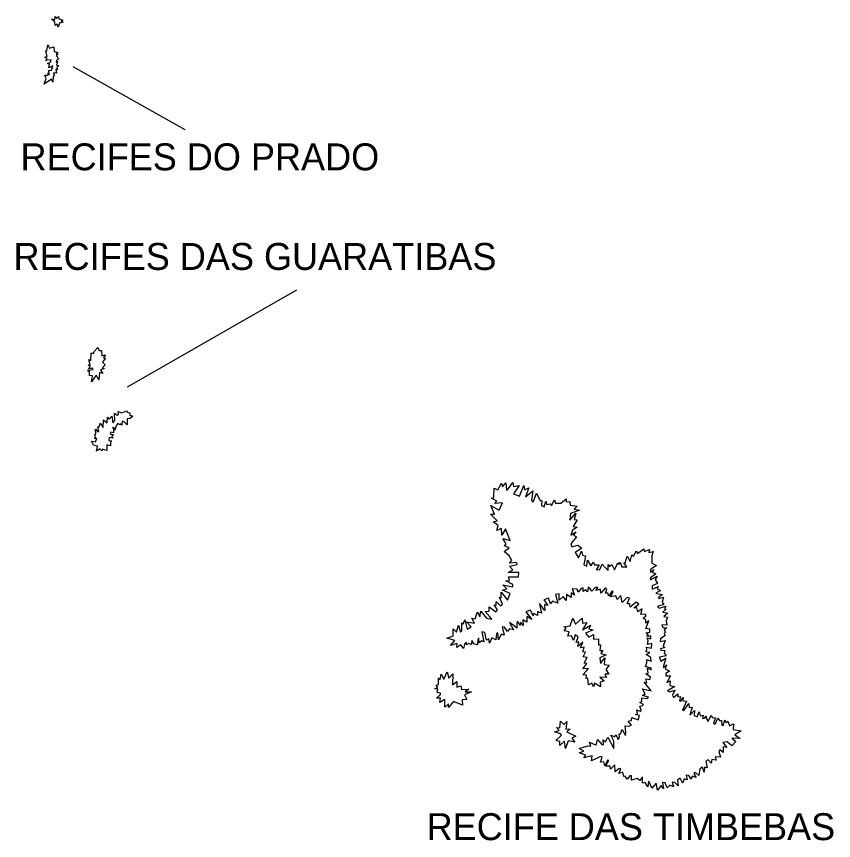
# Model space of a CAD drawing. Extents: x 662444 to 1640468, y 7452018 to 9606170.
# Drawn here: x 1121412 to 1141261, y 8052663 to 8072685 of the extents above; entities that cross this region are included whole.
import ezdxf

# ---------------------------------------------------------------- set-up
doc = ezdxf.new("R2010")
doc.units = 0
doc.layers.add('Level 1', color=7, linetype='Continuous')
doc.layers.add('Level 3', color=7, linetype='Continuous')

msp = doc.modelspace()

# ---------------------------------------------------------------- linework, layer by layer
at = {"layer": 'Level 1'}
for p, q in [((1125507, 8069931), (1122785, 8071458)), ((1128214, 8066038), (1124104, 8063682))]:
    msp.add_line(p, q, dxfattribs=at)
for points in [[(1122260, 8072631), (1122347, 8072603), (1122350, 8072685), (1122387, 8072635), (1122432, 8072685), (1122440, 8072626), (1122537, 8072593), (1122500, 8072576), (1122543, 8072544), (1122458, 8072523), (1122427, 8072429), (1122400, 8072497), (1122351, 8072467), (1122345, 8072550), (1122260, 8072631)], [(1122137, 8071178), (1122101, 8071261), (1122167, 8071259), (1122214, 8071294), (1122169, 8071303), (1122208, 8071325), (1122191, 8071374), (1122263, 8071382), (1122294, 8071487), (1122200, 8071440), (1122213, 8071529), (1122167, 8071546), (1122240, 8071575), (1122257, 8071634), (1122120, 8071613), (1122160, 8071649), (1122102, 8071694), (1122160, 8071716), (1122126, 8071847), (1122152, 8071848), (1122177, 8071996), (1122216, 8071913), (1122320, 8071947), (1122324, 8071834), (1122416, 8071813), (1122378, 8071776), (1122422, 8071772), (1122375, 8071732), (1122440, 8071659), (1122382, 8071620), (1122379, 8071579), (1122410, 8071596), (1122384, 8071504), (1122438, 8071498), (1122393, 8071443), (1122412, 8071393), (1122364, 8071395), (1122384, 8071307), (1122315, 8071317), (1122329, 8071256), (1122307, 8071227), (1122296, 8071088), (1122259, 8071160), (1122085, 8071044), (1122137, 8071178)], [(1123412, 8063854), (1123348, 8063969), (1123238, 8063811), (1123255, 8063956), (1123186, 8063960), (1123184, 8064041), (1123138, 8064082), (1123272, 8064107), (1123260, 8064138), (1123162, 8064118), (1123210, 8064183), (1123155, 8064213), (1123201, 8064214), (1123169, 8064352), (1123221, 8064325), (1123227, 8064515), (1123287, 8064493), (1123302, 8064544), (1123387, 8064642), (1123423, 8064568), (1123480, 8064572), (1123483, 8064436), (1123571, 8064462), (1123529, 8064391), (1123576, 8064383), (1123505, 8064288), (1123567, 8064222), (1123499, 8064154), (1123539, 8064131), (1123457, 8064099), (1123511, 8064014), (1123427, 8064034), (1123412, 8063854)], [(1123282, 8062267), (1123238, 8062365), (1123334, 8062350), (1123363, 8062434), (1123304, 8062435), (1123335, 8062462), (1123319, 8062527), (1123337, 8062537), (1123333, 8062660), (1123378, 8062604), (1123414, 8062599), (1123390, 8062714), (1123424, 8062716), (1123441, 8062805), (1123516, 8062696), (1123528, 8062884), (1123613, 8062808), (1123620, 8062948), (1123660, 8062901), (1123731, 8062976), (1123754, 8062814), (1123802, 8062869), (1123797, 8063049), (1123854, 8062999), (1123889, 8063026), (1123886, 8063090), (1123974, 8063052), (1124093, 8063102), (1124100, 8063069), (1124169, 8063057), (1124167, 8063000), (1124235, 8062973), (1124173, 8062914), (1124101, 8062908), (1124097, 8062762), (1124024, 8062832), (1123981, 8062855), (1123968, 8062755), (1123929, 8062786), (1123928, 8062761), (1123878, 8062794), (1123840, 8062754), (1123802, 8062652), (1123772, 8062707), (1123741, 8062680), (1123814, 8062644), (1123765, 8062640), (1123766, 8062569), (1123703, 8062585), (1123688, 8062545), (1123765, 8062518), (1123731, 8062496), (1123749, 8062438), (1123665, 8062453), (1123659, 8062380), (1123732, 8062372), (1123696, 8062340), (1123693, 8062255), (1123610, 8062279), (1123605, 8062138), (1123491, 8062172), (1123488, 8062130), (1123433, 8062183), (1123354, 8062121), (1123380, 8062246), (1123282, 8062267)], [(1132204, 8057419), (1132108, 8057352), (1132116, 8057454), (1131953, 8057404), (1132061, 8057522), (1131868, 8057578), (1132018, 8057636), (1132018, 8057807), (1132105, 8057726), (1132151, 8057899), (1132198, 8057726), (1132229, 8057761), (1132229, 8057950), (1132262, 8057919), (1132301, 8058022), (1132361, 8057798), (1132460, 8057857), (1132343, 8057980), (1132542, 8057943), (1132473, 8058069), (1132555, 8058046), (1132614, 8058218), (1132666, 8058096), (1132693, 8058234), (1132830, 8058064), (1132959, 8058045), (1132917, 8058087), (1132795, 8058226), (1132893, 8058236), (1132896, 8058338), (1133060, 8058222), (1133095, 8058269), (1133020, 8058389), (1133064, 8058385), (1133069, 8058474), (1133173, 8058366), (1133219, 8058409), (1133144, 8058572), (1133187, 8058558), (1133183, 8058696), (1133337, 8058506), (1133403, 8058667), (1133223, 8058742), (1133323, 8058780), (1133226, 8058877), (1133473, 8058824), (1133469, 8058885), (1133300, 8058970), (1133388, 8058982), (1133362, 8059073), (1133611, 8059071), (1133618, 8059179), (1133358, 8059176), (1133470, 8059239), (1133387, 8059331), (1133573, 8059369), (1133566, 8059415), (1133392, 8059402), (1133445, 8059464), (1133379, 8059584), (1133262, 8059685), (1133384, 8059773), (1133268, 8059823), (1133310, 8059870), (1133224, 8060005), (1133407, 8059952), (1133290, 8060239), (1133206, 8060083), (1133192, 8060242), (1133080, 8060197), (1133115, 8060318), (1132989, 8060409), (1133090, 8060429), (1132927, 8060592), (1133027, 8060592), (1132938, 8060802), (1133142, 8060686), (1133220, 8060865), (1133034, 8060852), (1133082, 8060910), (1132949, 8060983), (1133008, 8060994), (1133014, 8061224), (1133019, 8061224), (1133110, 8061184), (1133194, 8061342), (1133222, 8061255), (1133302, 8061350), (1133320, 8061177), (1133344, 8061187), (1133467, 8061358), (1133487, 8061267), (1133621, 8061292), (1133487, 8061086), (1133629, 8061026), (1133736, 8061289), (1133751, 8061184), (1133858, 8061229), (1133779, 8061011), (1133953, 8061157), (1133921, 8060928)], [(1133921, 8060928), (1133966, 8060885), (1134044, 8061099), (1134131, 8060917), (1134172, 8060921), (1134164, 8060801), (1134229, 8060768), (1134272, 8060910), (1134300, 8060830), (1134378, 8060847), (1134412, 8060802), (1134485, 8060938), (1134508, 8060863), (1134639, 8060858), (1134766, 8060966), (1134763, 8060895), (1134859, 8060902), (1134861, 8060811), (1135037, 8060790), (1134963, 8060717), (1135091, 8060689), (1134873, 8060612), (1134856, 8060449), (1134999, 8060617), (1134961, 8060459), (1135030, 8060453), (1134939, 8060289), (1135033, 8060273), (1134923, 8060205), (1134877, 8060080), (1135004, 8060164), (1134946, 8060084), (1135018, 8060040), (1134879, 8059868), (1134900, 8059798), (1135046, 8059840), (1135144, 8059766), (1134985, 8059658), (1135063, 8059531), (1135135, 8059694), (1135160, 8059594), (1135239, 8059584), (1135195, 8059363), (1135266, 8059333), (1135288, 8059478), (1135364, 8059338), (1135427, 8059428), (1135456, 8059358), (1135569, 8059360), (1135499, 8059242), (1135586, 8059247), (1135638, 8059379), (1135716, 8059298), (1135790, 8059226), (1135790, 8059366), (1135817, 8059322), (1135872, 8059367), (1135937, 8059243), (1136022, 8059414), (1136044, 8059367), (1136075, 8059425), (1136116, 8059309), (1136236, 8059311), (1136168, 8059410), (1136203, 8059409), (1136249, 8059575), (1136325, 8059446), (1136365, 8059604), (1136406, 8059575), (1136471, 8059701), (1136496, 8059639), (1136654, 8059752), (1136659, 8059688), (1136789, 8059738), (1136771, 8059659), (1136882, 8059687), (1136849, 8059586), (1136849, 8059401), (1136960, 8059342), (1136820, 8059254), (1136819, 8059231), (1136815, 8059177), (1136898, 8059246), (1136858, 8059186), (1136942, 8059143), (1136818, 8059049), (1136812, 8058995), (1136973, 8059086), (1136928, 8059002), (1136982, 8058906), (1136857, 8058851), (1136854, 8058767), (1137000, 8058839), (1136975, 8058776), (1137056, 8058740), (1136941, 8058677), (1136964, 8058666), (1137104, 8058637), (1137010, 8058570), (1137017, 8058545), (1137128, 8058572)], [(1136248, 8058414), (1136305, 8058554), (1136252, 8058569), (1136126, 8058449), (1136095, 8058618), (1136009, 8058516), (1135976, 8058612), (1135842, 8058587), (1135904, 8058709), (1135885, 8058727), (1135800, 8058601), (1135778, 8058670), (1135719, 8058670), (1135752, 8058761), (1135723, 8058800), (1135609, 8058676), (1135597, 8058768), (1135483, 8058738), (1135536, 8058814), (1135474, 8058807), (1135392, 8058723), (1135352, 8058775), (1135300, 8058817), (1135287, 8058707), (1135247, 8058757), (1135182, 8058710), (1135179, 8058801), (1135128, 8058789), (1135059, 8058701), (1135032, 8058771), (1134915, 8058777), (1134972, 8058621), (1134886, 8058685), (1134884, 8058565), (1134773, 8058638), (1134766, 8058492), (1134692, 8058591), (1134600, 8058504), (1134599, 8058660), (1134506, 8058639), (1134562, 8058433), (1134435, 8058478), (1134382, 8058410), (1134334, 8058552), (1134223, 8058507), (1134322, 8058374), (1134243, 8058394), (1134244, 8058253), (1134118, 8058424), (1134136, 8058333), (1134168, 8058188), (1134069, 8058229), (1134067, 8058132), (1133976, 8058175), (1133964, 8058120), (1133901, 8058257), (1133790, 8058217), (1133931, 8058031), (1133810, 8058104), (1133813, 8057968), (1133713, 8058024), (1133719, 8057889), (1133654, 8057972), (1133650, 8057893), (1133587, 8057990), (1133569, 8057933), (1133566, 8057823), (1133504, 8057882), (1133388, 8057959), (1133486, 8057785), (1133392, 8057803), (1133344, 8057742), (1133269, 8057847), (1133213, 8057853), (1133262, 8057655), (1133188, 8057675), (1133120, 8057536), (1133109, 8057709), (1133073, 8057686), (1133054, 8057541), (1132960, 8057584), (1132905, 8057462), (1132888, 8057565), (1132828, 8057532), (1132792, 8057714), (1132716, 8057736), (1132763, 8057493), (1132720, 8057517), (1132652, 8057465), (1132645, 8057580), (1132621, 8057550), (1132609, 8057415), (1132523, 8057438), (1132474, 8057526), (1132459, 8057422), (1132403, 8057454), (1132345, 8057420), (1132342, 8057471), (1132308, 8057457), (1132271, 8057330), (1132204, 8057419)], [(1137128, 8058572), (1137102, 8058457), (1137139, 8058401), (1136986, 8058349), (1137024, 8058309), (1137184, 8058360), (1137154, 8058290), (1137195, 8058287), (1137113, 8058215), (1137239, 8058185), (1137139, 8058104), (1137228, 8058093), (1137194, 8058000), (1137209, 8057899), (1137094, 8057903), (1137113, 8057841), (1137212, 8057828), (1137150, 8057781), (1137177, 8057729), (1137145, 8057689), (1137174, 8057644), (1137055, 8057566), (1137050, 8057502), (1137174, 8057524), (1137121, 8057384), (1137166, 8057351), (1137058, 8057323), (1137065, 8057284), (1137164, 8057281), (1137145, 8057222), (1137194, 8057150), (1137036, 8057116), (1137065, 8057022), (1137187, 8057091), (1137133, 8056911), (1137132, 8056857), (1137201, 8056929), (1137172, 8056833), (1137273, 8056775), (1137185, 8056721), (1137190, 8056661), (1137300, 8056661), (1137212, 8056502), (1137294, 8056540), (1137284, 8056426), (1137403, 8056402), (1137231, 8056302), (1137278, 8056273), (1137409, 8056315), (1137352, 8056194), (1137376, 8056139), (1137478, 8056226), (1137479, 8056157), (1137541, 8056160), (1137518, 8056064), (1137542, 8056040), (1137606, 8056140), (1137604, 8056061), (1137686, 8056051), (1137590, 8055829), (1137621, 8055822), (1137746, 8055995), (1137751, 8055896), (1137825, 8055902), (1137769, 8055707), (1137882, 8055821), (1137879, 8055697), (1137945, 8055665), (1137997, 8055789), (1138022, 8055691), (1138091, 8055712), (1138077, 8055626), (1138125, 8055632), (1138167, 8055682), (1138171, 8055634), (1138218, 8055558), (1138289, 8055709), (1138316, 8055653), (1138392, 8055646), (1138345, 8055518), (1138385, 8055489), (1138453, 8055634), (1138491, 8055581), (1138542, 8055582), (1138546, 8055462), (1138584, 8055458), (1138619, 8055597), (1138652, 8055525), (1138692, 8055561), (1138735, 8055446), (1138832, 8055495), (1138820, 8055364), (1139017, 8055331), (1138865, 8055230), (1138990, 8055139), (1138793, 8055152), (1138886, 8055070), (1138788, 8054961), (1138676, 8055059), (1138570, 8055046), (1138667, 8054926)], [(1135296, 8054966), (1135368, 8054959), (1135331, 8055055), (1135497, 8054983), (1135526, 8055121), (1135630, 8054998), (1135673, 8054988), (1135661, 8055107), (1135719, 8055064), (1135776, 8055178), (1135922, 8054897), (1135925, 8055076), (1135855, 8055226), (1135950, 8055181), (1135970, 8055239), (1136033, 8055119), (1136063, 8055177), (1136052, 8055257), (1136088, 8055256), (1136127, 8055358), (1136210, 8055217), (1136212, 8055288), (1136201, 8055448), (1136285, 8055440), (1136353, 8055464), (1136273, 8055566), (1136354, 8055579), (1136358, 8055653), (1136515, 8055595), (1136544, 8055700), (1136445, 8055725), (1136496, 8055733), (1136483, 8055839), (1136582, 8055797), (1136589, 8055828), (1136553, 8055930), (1136624, 8055940), (1136643, 8055970), (1136555, 8056014), (1136607, 8056040), (1136607, 8056130), (1136729, 8056116), (1136763, 8056145), (1136621, 8056188), (1136684, 8056228), (1136618, 8056347), (1136834, 8056298), (1136770, 8056377), (1136658, 8056507), (1136722, 8056497), (1136701, 8056588), (1136801, 8056577), (1136816, 8056635), (1136700, 8056710), (1136757, 8056732), (1136746, 8056832), (1136745, 8056852), (1136828, 8056814), (1136829, 8056847), (1136692, 8056895), (1136728, 8056979), (1136728, 8057061), (1136835, 8057019), (1136827, 8057109), (1136711, 8057184), (1136763, 8057213), (1136799, 8057232), (1136712, 8057245), (1136728, 8057317), (1136720, 8057357), (1136843, 8057333), (1136846, 8057451), (1136741, 8057427), (1136758, 8057518), (1136737, 8057585), (1136821, 8057567), (1136825, 8057631), (1136718, 8057632), (1136755, 8057669), (1136702, 8057706), (1136795, 8057726), (1136799, 8057798), (1136699, 8057812), (1136738, 8057897), (1136777, 8057998), (1136698, 8057944), (1136702, 8058013), (1136633, 8058072), (1136706, 8058121), (1136687, 8058159), (1136584, 8058152), (1136598, 8058209), (1136616, 8058289), (1136504, 8058216), (1136486, 8058319), (1136414, 8058313), (1136532, 8058406), (1136469, 8058452), (1136317, 8058329), (1136314, 8058413), (1136248, 8058414)], [(1135612, 8057210), (1135734, 8057172), (1135588, 8057102), (1135598, 8056964), (1135709, 8057104), (1135692, 8056943), (1135807, 8056920), (1135732, 8056816), (1135801, 8056705), (1135706, 8056707), (1135744, 8056625), (1135581, 8056632), (1135686, 8056542), (1135593, 8056508), (1135604, 8056396), (1135453, 8056487), (1135434, 8056398), (1135387, 8056486), (1135306, 8056445), (1135293, 8056611), (1135254, 8056602), (1135257, 8056679), (1135173, 8056692), (1135255, 8056781), (1135312, 8056841), (1135169, 8056837), (1135267, 8056962), (1135201, 8056974), (1135274, 8057113), (1135177, 8057126), (1135236, 8057243), (1135167, 8057249), (1135203, 8057361), (1135116, 8057345), (1135169, 8057483), (1135048, 8057381), (1135072, 8057490), (1135007, 8057474), (1135060, 8057611), (1134987, 8057664), (1134942, 8057524), (1134896, 8057636), (1134806, 8057628), (1134835, 8057730), (1134715, 8057756), (1134769, 8057829), (1134713, 8057853), (1134862, 8057879), (1134929, 8058062), (1134994, 8057920), (1135154, 8058064), (1135159, 8057944), (1135269, 8057963), (1135166, 8057782), (1135359, 8057894), (1135316, 8057806), (1135423, 8057783), (1135233, 8057701), (1135316, 8057606), (1135433, 8057667), (1135431, 8057552), (1135552, 8057566), (1135549, 8057421), (1135604, 8057417), (1135588, 8057279), (1135660, 8057283), (1135612, 8057210)], [(1132033, 8056038), (1131904, 8055899), (1131906, 8055985), (1131822, 8055901), (1131817, 8056091), (1131694, 8056018), (1131715, 8056122), (1131618, 8056125), (1131715, 8056214), (1131714, 8056247), (1131632, 8056257), (1131652, 8056344), (1131578, 8056348), (1131651, 8056389), (1131611, 8056436), (1131668, 8056456), (1131668, 8056609), (1131702, 8056575), (1131726, 8056707), (1131792, 8056585), (1131874, 8056762), (1131915, 8056605), (1132014, 8056712), (1132008, 8056446), (1132108, 8056525), (1132109, 8056387), (1132208, 8056425), (1132224, 8056333), (1132403, 8056340), (1132314, 8056272), (1132467, 8056273), (1132296, 8056200), (1132353, 8056086), (1132237, 8056082), (1132249, 8055950), (1132033, 8056038)], [(1134649, 8055220), (1134630, 8055258), (1134485, 8055303), (1134596, 8055340), (1134532, 8055409), (1134609, 8055399), (1134631, 8055563), (1134709, 8055481), (1134779, 8055556), (1134759, 8055368), (1134867, 8055380), (1134783, 8055300), (1135003, 8055200), (1134904, 8055148), (1134973, 8055054), (1134813, 8055089), (1134753, 8054902), (1134728, 8055076), (1134615, 8054975), (1134609, 8055070), (1134513, 8055097), (1134649, 8055220)], [(1138667, 8054926), (1138577, 8054937), (1138581, 8054803), (1138501, 8054865), (1138477, 8054829), (1138519, 8054685), (1138389, 8054696), (1138412, 8054616), (1138305, 8054632), (1138287, 8054545), (1138213, 8054627), (1138163, 8054592), (1138194, 8054433), (1138128, 8054447), (1138115, 8054325), (1138075, 8054449), (1138012, 8054402), (1137989, 8054243), (1137912, 8054317), (1137867, 8054293), (1137924, 8054196), (1137830, 8054223), (1137805, 8054151), (1137748, 8054245), (1137679, 8054252), (1137704, 8054137), (1137633, 8054159), (1137600, 8054065), (1137592, 8054066), (1137534, 8054180), (1137473, 8054127), (1137490, 8053991), (1137403, 8054076), (1137342, 8054082), (1137377, 8053967), (1137283, 8054008), (1137218, 8053940), (1137169, 8054067), (1137109, 8054069), (1137130, 8053919), (1137073, 8054003), (1136982, 8053890), (1136955, 8054057), (1136848, 8053932), (1136798, 8054060), (1136766, 8054101), (1136752, 8053969), (1136686, 8054070), (1136618, 8054054), (1136620, 8054212), (1136554, 8054120), (1136488, 8054171), (1136354, 8054133), (1136355, 8054233), (1136313, 8054234), (1136245, 8054154), (1136203, 8054226), (1136167, 8054217), (1136146, 8054323), (1136043, 8054293), (1136095, 8054401), (1136054, 8054415), (1135954, 8054331), (1135952, 8054495), (1135942, 8054497), (1135841, 8054396), (1135833, 8054469), (1135725, 8054473), (1135801, 8054604), (1135768, 8054613), (1135708, 8054481), (1135679, 8054574), (1135600, 8054566), (1135642, 8054692), (1135604, 8054707), (1135489, 8054648), (1135383, 8054600), (1135397, 8054722), (1135198, 8054674), (1135246, 8054737), (1135081, 8054790), (1135195, 8054835), (1135086, 8054900), (1135296, 8054966)]]:
    msp.add_lwpolyline(points, dxfattribs=at)

# ---------------------------------------------------------------- texts
at = {"layer": 'Level 3'}
for s, height, p in [('RECIFES DO PRADO', 655.2, (1121510, 8068947)), ('RECIFES DAS GUARATIBAS', 655.14, (1121340, 8066527)), ('RECIFE DAS TIMBEBAS', 654.8, (1131376, 8052672))]:
    msp.add_text(s, height=height, dxfattribs=at).set_placement(p)

doc.saveas('drawing.dxf')
